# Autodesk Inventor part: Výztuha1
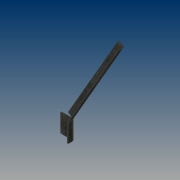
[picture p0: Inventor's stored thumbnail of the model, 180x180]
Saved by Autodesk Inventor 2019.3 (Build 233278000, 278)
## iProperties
Created: 2019-02
Part Number: Výztuha1
Material: Ocel, měkká, svařovaná
Document SubType Name: Plech
Designer: B-hon
Density: 7.85 g/cm^3
Sheet Metal Rule: Výchozí_mm
Appearance: Plech
Author: B-hon
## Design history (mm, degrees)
node "Plocha1"
  sketch "Náčrt1"
    geometry: L1 (-7, 0)-(-48, 0); L2 (-48, 0)-(-48, 390); L3 (-7, 390)-(-7, 0); L4 (-48, 390)-(-7, 390); 5 further points
    constraints: 8 end point, 2 horizontal alignment, 1 horizontal, 1 parallel, 1 perpendicular
    dimensions: "d5" = 7 vertical distance of point (0, 0) point (-17, 7); "d6" = 17 horizontal distance of point (0, 0) point (-17, 7); "d7" = 21 distance of point (-38, 7) point (-17, 7); "d8" = 45 vertical distance of point (-17, 7) point (-27.5, 52); "d9" = 10.5 horizontal distance of point (-17, 7) point (-27.5, 52) (= 0.5 x d7); "d10" = 10 distance from line of point (-17, 7) L3; "d11" = 10 distance from line of point (-38, 7) L2 (= d10); "d12" = 250 distance from line of L3 point (243, 370); "d13" = 370 distance from line of L1 point (243, 370); "d15" = 390 distance of L1.end L2.end
node "Obruba3"
sketch "Náčrt5"
  geometry: L1 (-28.904, 62)-(-14, 62); L2 (-14, 62)-(-14, 60); L3 (-14, 60)-(-28.904, 60); L4 (-28.904, 60)-(-28.904, 62); L5 (-14, 0)-(0, 0) reference; L6 (-14, 390)-(-14, 0) reference; 1 further point
  constraints: 8 end point, 2 parallel, 1 horizontal, 1 perpendicular
  dimensions: "d50" = 60 distance between parallel lines of L5 L3; "d51" = 2 distance of L1.end L2.end; "d52" = 0 distance between parallel lines of L6 L2
extrude "Vysunutí1" cut sketch "Náčrt5" stored distance "d53" = 200; taper "d54" = 0 deg
node "Upravit přímo1"
sketch "Náčrt6"
  geometry: L1 (-9.893, 60)-(57.958, 60); L2 (17, 60)-(20, 60) reference; 1 further point
  constraints: 2 end point, 1 collinear
  dimensions: "d58" = 0 distance between parallel lines of L1 L2
feature "Ohyb součásti1" sketch "Náčrt6" dims "d59" = 3, "d60" = 30 deg
sketch "Náčrt7"
  geometry: L1 (13, 0)-(48, 0) reference; 4 further points
  constraints: 1 horizontal alignment
  dimensions: "d61" = 7 distance from line of L1 point (21, 7); "d62" = 21 horizontal distance of point (0, 0) point (21, 7); "d63" = 21 distance of point (42, 7) point (21, 7); "d64" = 10.5 horizontal distance of point (42, 7) point (31.5, 52) (= 0.5 x d63); "d65" = 45 vertical distance of point (42, 7) point (31.5, 52)
hole "Díra1" sketch "Náčrt7" at (21, 7), (42, 7), (31.5, 52) diameter "d66" = 5.5; stored, may be unused: countersink angle "d70" = 90 deg, drill point angle "d72" = 0 deg; dims "d67" = 6, "d68" = 4, "d69" = 2, "d71" = 3 (= Tloušťka)
node "Upravit přímo2"
node "Těleso1"
feature "Deska1" dims "d14" = 3 (= Tloušťka)
sketch "Náčrt4"
  geometry: L1 through (-195, 0) direction (1, 0); L2 through (0, 10) direction (-3.35e-32, 1); L3 (0, 20)-(-390, 20); L4 (-390, 20)-(-390, 0)
  constraints: 6 end point, 1 horizontal, 1 perpendicular, 1 vertical
feature "Deska4" dims "d14" = 3 (= Tloušťka), "d40" = 3 (= ŠířkaVýštipu), "d41" = 1.5 (= HloubkaVýštipu), "d42" = 6 (= MinimálníZbytek), "d43" = 3 (= PřechodovýPoloměr), "d44" = 20, "d45" = 90 deg, "d46" = 3 (= PoloměrOhybu), "d47" = 12 (= VelikostRohovéhoVýštipu), "d48" = 3 (= VelikostMezery), "d49" = 3 (= VelikostJacobihoPoloměru), "MezeraVystřižení" = 0.01
feature "Ohyb3" dims "d14" = 3 (= Tloušťka), "d40" = 3 (= ŠířkaVýštipu), "d41" = 1.5 (= HloubkaVýštipu), "d42" = 6 (= MinimálníZbytek), "d43" = 3 (= PřechodovýPoloměr), "d44" = 20, "d45" = 90 deg, "d46" = 3 (= PoloměrOhybu), "MezeraVystřižení" = 0.01
feature "Roh3" dims "d44" = 20, "d45" = 90 deg, "d47" = 12 (= VelikostRohovéhoVýštipu), "d48" = 3 (= VelikostMezery), "d49" = 3 (= VelikostJacobihoPoloměru)
feature "Posunout1" dims "d57" = -20
feature "Posunout2" dims "d75" = 1
other parameters: "Tloušťka" = 3 (derived), "KSoučinitel" = 4.4, "PoloměrOhybu" = 3 (= Tloušťka), "ŠířkaVýštipu" = 3 (= Tloušťka), "HloubkaVýštipu" = 1.5 (= 0.5 x Tloušťka), "VelikostRohovéhoVýštipu" = 12 (= 4 x Tloušťka), "MinimálníZbytek" = 6 (= 2 x Tloušťka), "PřechodovýPoloměr" = 3 (= PoloměrOhybu), "VelikostJacobihoPoloměru" = 3 (= PoloměrOhybu), "VelikostMezery" = 3 (= Tloušťka), "d55" = 0, "d56" = 0, "d73" = 0, "d74" = 0
